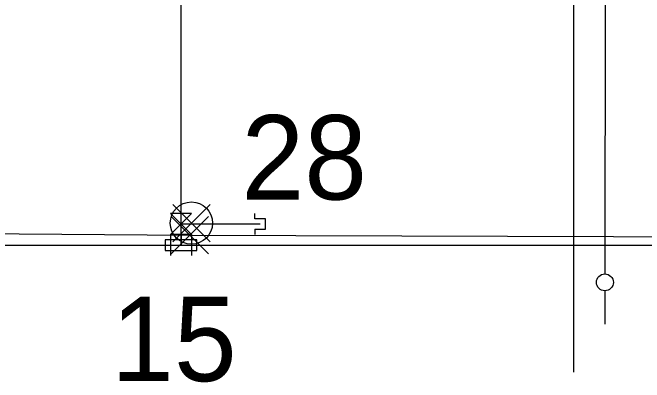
# Model space of a CAD drawing. Extents: x -263964 to -263544, y -1242317 to -1242020.
# Drawn here: x -263832.36 to -263817.39, y -1242253.39 to -1242244.63 of the extents above; entities that cross this region are included whole.
import ezdxf

# ---------------------------------------------------------------- set-up
doc = ezdxf.new("R2010")
doc.units = 0
for name, color, linetype in [('KFA_KOORDINACNA_SITUACIA_DSP_SEDA', 7, 'Continuous'), ('KFA_SO_50-1-II_BODY', 7, 'Continuous'), ('KFA_SO_50-1-II_SUPATKA', 7, 'Continuous'), ('KFA_SO_50-1-II_VODOVODNE_PRIPOJKY_PROJEKT', 7, 'Continuous'), ('KFA_SO_50-2_POZIARNY_VODOVOD_TRASA', 7, 'Continuous')]:
    doc.layers.add(name, color=color, linetype=linetype)

msp = doc.modelspace()

# ---------------------------------------------------------------- linework, layer by layer
at = {"layer": 'KFA_KOORDINACNA_SITUACIA_DSP_SEDA'}
for p, q in [((-263828.368, -1242249.39), (-263828.368, -1242235.757)), ((-263818.318, -1242235.757), (-263818.321, -1242250.822)), ((-263819.068, -1242241.132), (-263819.068, -1242253.146)), ((-263828.118, -1242249.39), (-263828.618, -1242249.39)), ((-263828.618, -1242249.89), (-263828.118, -1242249.39)), ((-263828.618, -1242249.39), (-263828.118, -1242249.89)), ((-263826.618, -1242249.515), (-263826.618, -1242249.39)), ((-263826.368, -1242249.515), (-263826.618, -1242249.515)), ((-263826.368, -1242249.765), (-263826.368, -1242249.515)), ((-263828.368, -1242249.64), (-263826.493, -1242249.64)), ((-263828.118, -1242249.89), (-263828.618, -1242249.89)), ((-263828.618, -1242249.89), (-263828.618, -1242250.39)), ((-263828.368, -1242250.14), (-263828.368, -1242249.89)), ((-263828.368, -1242249.89), (-263828.368, -1242250.14)), ((-263828.118, -1242249.89), (-263828.118, -1242250.39)), ((-263826.618, -1242249.765), (-263826.618, -1242249.89)), ((-263826.618, -1242249.765), (-263826.368, -1242249.765)), ((-263827.993, -1242250.015), (-263828.743, -1242250.015)), ((-263828.743, -1242250.015), (-263828.743, -1242250.265)), ((-263827.993, -1242250.265), (-263827.993, -1242250.015)), ((-263924.143, -1242250.14), (-263788.143, -1242250.14)), ((-263828.743, -1242250.265), (-263827.993, -1242250.265)), ((-263818.322, -1242251.222), (-263818.322, -1242252.009))]:
    msp.add_line(p, q, dxfattribs=at)
msp.add_circle((-263818.322, -1242251.022), 0.2, dxfattribs=at)
at = {"layer": 'KFA_SO_50-1-II_BODY'}
for p, q in [((-263828.563, -1242250.061), (-263827.679, -1242249.177)), ((-263827.679, -1242250.061), (-263828.563, -1242249.177)), ((-263828.604, -1242250.343), (-263827.72, -1242249.459)), ((-263827.72, -1242250.343), (-263828.604, -1242249.459))]:
    msp.add_line(p, q, dxfattribs=at)
at = {"layer": 'KFA_SO_50-1-II_SUPATKA'}
msp.add_circle((-263828.121, -1242249.619), 0.5, dxfattribs=at)
at = {"layer": 'KFA_SO_50-1-II_VODOVODNE_PRIPOJKY_PROJEKT'}
msp.add_line((-263828.368, -1242250.14), (-263828.368, -1242235.757), dxfattribs=at)
at = {"layer": 'KFA_SO_50-2_POZIARNY_VODOVOD_TRASA'}
msp.add_lwpolyline([(-263924.479, -1242117.427), (-263924.931, -1242185.127), (-263924.146, -1242197.091), (-263924.185, -1242203.3), (-263924.296, -1242220.899), (-263924.1, -1242250.121), (-263913.986, -1242249.798), (-263886.91, -1242249.876), (-263867.714, -1242249.83), (-263837.257, -1242249.836), (-263828.162, -1242249.901), (-263787.99, -1242250.032), (-263788.202, -1242220.837), (-263788.195, -1242200.509), (-263788.092, -1242179.915), (-263788.062, -1242148.958), (-263787.919, -1242127.952)], dxfattribs=at)

# ---------------------------------------------------------------- texts
at = {"layer": 'KFA_SO_50-1-II_BODY'}
for s, p in [('28', (-263826.935, -1242249.061)), ('15', (-263830.022, -1242253.362))]:
    msp.add_text(s, height=2, dxfattribs=at).set_placement(p)

doc.saveas('drawing.dxf')
